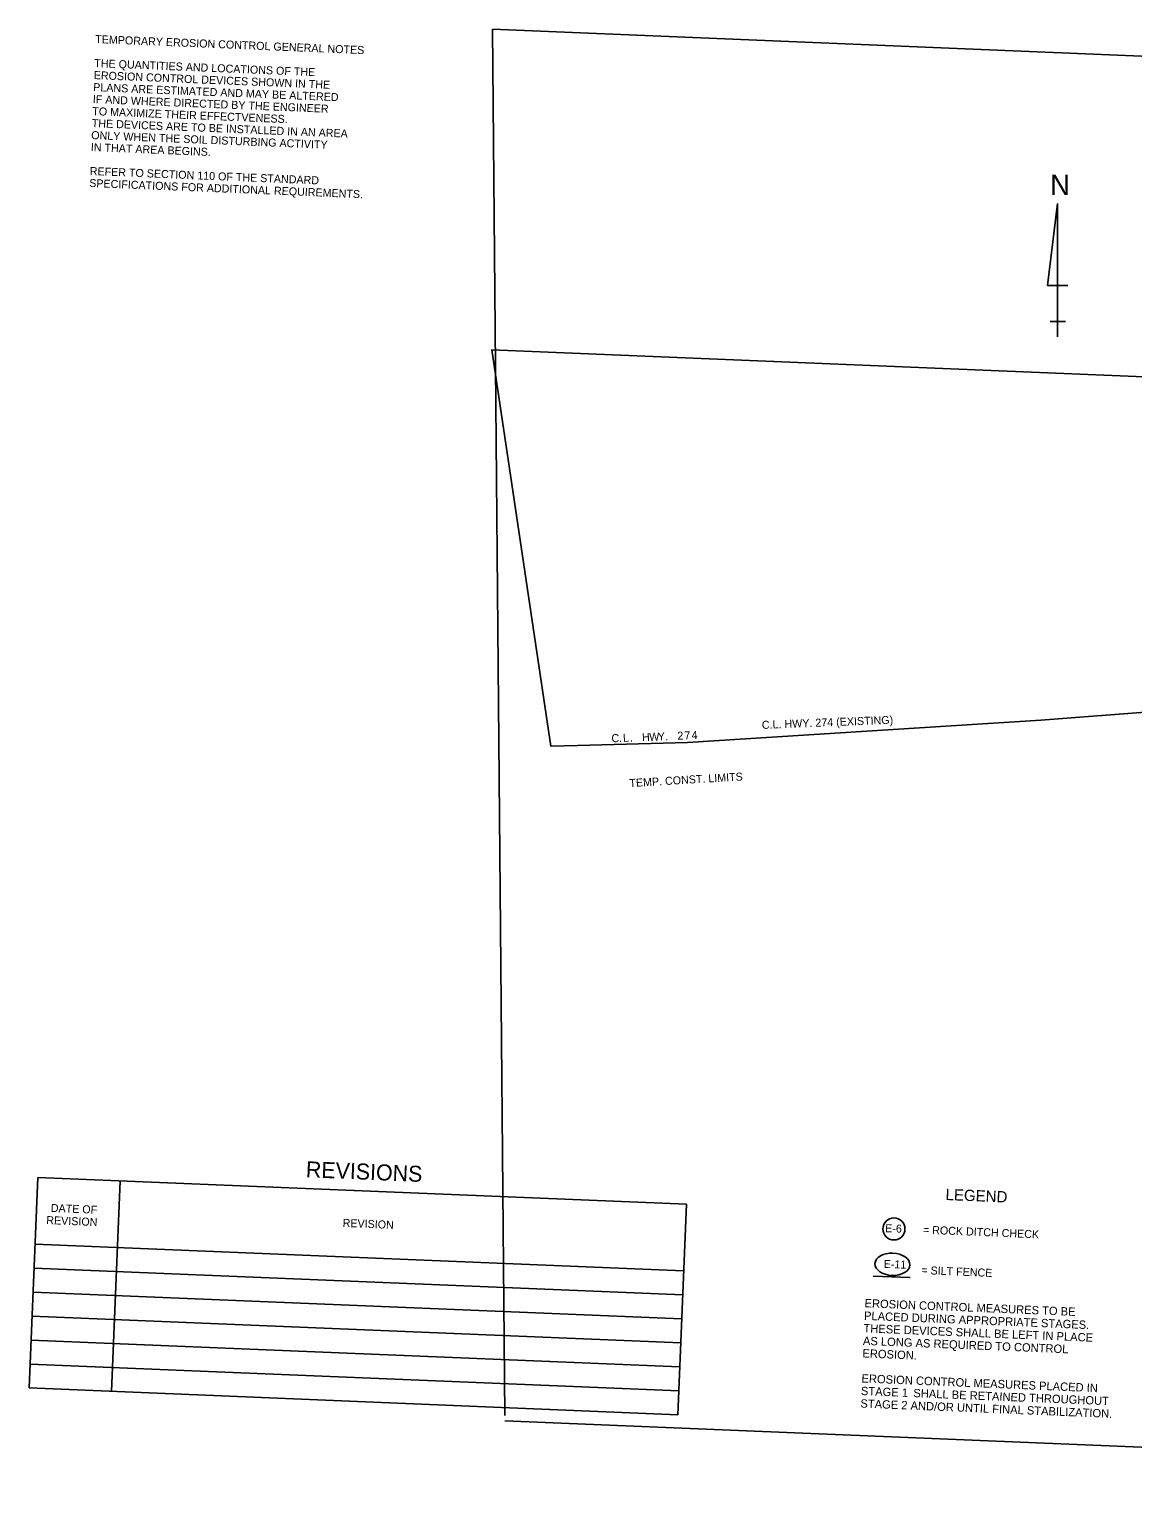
# Model space of a CAD drawing. Extents: x 1141837 to 1143465, y 1657046 to 1658140.
import ezdxf

# ---------------------------------------------------------------- set-up
doc = ezdxf.new("R2010")
doc.units = 0
for name, color, linetype in [('Default', 7, 'Continuous'), ('E_No Plot', 7, 'Continuous'), ('R_Annotation', 7, 'Continuous'), ('R_Erosion', 7, 'Continuous'), ('R_No Plot', 7, 'Continuous'), ('S_BASELINE', 7, 'Continuous')]:
    doc.layers.add(name, color=color, linetype=linetype)

msp = doc.modelspace()

# ---------------------------------------------------------------- linework, layer by layer
at = {"layer": 'Default'}
for p, q in [((1142608.2, 1658009.3), (1142600.5, 1657947.8)), ((1142608.2, 1657909.3), (1142608.2, 1658009.3)), ((1142608.2, 1658009.3), (1142608.2, 1657932.4)), ((1142600.5, 1657947.8), (1142615.9, 1657947.8)), ((1142608.2, 1657909.3), (1142608.2, 1657932.4)), ((1142608.2, 1657920.8), (1142602.5, 1657920.8)), ((1142602.5, 1657920.8), (1142614, 1657920.8)), ((1142608.2, 1657909.3), (1142608.2, 1657920.8))]:
    msp.add_line(p, q, dxfattribs=at)
at = {"layer": 'E_No Plot'}
msp.add_lwpolyline([(1142248.2, 1657602.9), (1142228.1, 1657602.5), (1142228.1, 1657602.5), (1142183.9, 1657899.7), (1143071.8, 1657863), (1143063.8, 1657668.7), (1142853.2, 1657641.8), (1142595.6, 1657621.9), (1142330.5, 1657605.2)], close=True, dxfattribs=at)
at = {"layer": 'R_Erosion'}
msp.add_lwpolyline([(1142469.9, 1657205.2), (1142497.6, 1657204)], dxfattribs=at)
msp.add_circle((1142485.4, 1657240.5), 8.26, dxfattribs=at)
msp.add_ellipse((1142484.3, 1657214), major_axis=(13.1, -0.5), ratio=0.638788, dxfattribs=at)
at = {"layer": 'R_No Plot'}
for p, q in [((1142184.3, 1658140.1), (1142193.6, 1657100.5)), ((1143465.2, 1658087.1), (1142184.3, 1658140.1)), ((1142193.7, 1657096.5), (1143422.1, 1657045.7))]:
    msp.add_line(p, q, dxfattribs=at)
at = {"layer": 'S_BASELINE'}
for p, q in [((1141843.4, 1657279.1), (1141836.9, 1657121.3)), ((1141843.4, 1657279.1), (1142329.8, 1657259)), ((1141905.2, 1657276.6), (1141898.6, 1657118.7)), ((1142329.8, 1657259), (1142323.3, 1657101.1)), ((1141841.3, 1657229.2), (1142327.7, 1657209)), ((1141840.6, 1657211.2), (1142327, 1657191.1)), ((1141839.8, 1657193.2), (1142326.2, 1657173.1)), ((1141839.1, 1657175.2), (1142325.5, 1657155.1)), ((1141838.4, 1657157.2), (1142324.7, 1657137.1)), ((1141837.6, 1657139.2), (1142324, 1657119.1)), ((1141836.9, 1657121.3), (1142323.3, 1657101.1))]:
    msp.add_line(p, q, dxfattribs=at)

# ---------------------------------------------------------------- texts
at = {"layer": 'Default'}
msp.add_text('N', height=15.4, dxfattribs=at).set_placement((1142602.6, 1658015.7))
at = {"layer": 'R_Annotation'}
for s, height, rotation, p in [('TEMPORARY EROSION CONTROL GENERAL NOTES', 6, 357.6311, (1141886.3, 1658129.7)), ('THE QUANTITIES AND LOCATIONS OF THE', 6, 357.6311, (1141885.6, 1658111.7)), ('EROSION CONTROL DEVICES SHOWN IN THE ', 6, 357.6311, (1141885.2, 1658102.7)), ('PLANS ARE ESTIMATED AND MAY BE ALTERED ', 6, 357.6311, (1141884.8, 1658093.7)), ('IF AND WHERE DIRECTED BY THE ENGINEER ', 6, 357.6311, (1141884.5, 1658084.7)), ('THE DEVICES ARE TO BE INSTALLED IN AN AREA ', 6, 357.6311, (1141883.7, 1658066.7)), ('TO MAXIMIZE THEIR EFFECTVENESS. ', 6, 357.6311, (1141884.1, 1658075.7)), ('ONLY WHEN THE SOIL DISTURBING ACTIVITY', 6, 357.6311, (1141883.3, 1658057.7)), ('IN THAT AREA BEGINS.', 6, 357.6311, (1141883, 1658048.7)), ('REFER TO SECTION 110 OF THE STANDARD ', 6, 357.6311, (1141882.2, 1658030.8)), ('SPECIFICATIONS FOR ADDITIONAL REQUIREMENTS.', 6, 357.6311, (1141881.8, 1658021.8)), ('C.L. HWY. 274 (EXISTING) ', 6, 2.2818, (1142386.5, 1657615.4)), ('H', 6, 2.1287, (1142296.6, 1657606.2)), ('W', 6, 2.1827, (1142302, 1657606.4)), ('Y', 6, 2.247, (1142308.4, 1657606.7)), ('2', 6, 2.3941, (1142323.1, 1657607.3)), ('7', 6, 2.4481, (1142328.4, 1657607.5)), ('4', 6, 2.502, (1142333.8, 1657607.7)), ('C', 6, 1.8993, (1142273.7, 1657605.4)), ('.', 6, 1.9561, (1142279.3, 1657605.6)), ('L', 6, 1.9854, (1142282.3, 1657605.7)), ('.', 6, 2.0393, (1142287.6, 1657605.9)), ('.', 6, 2.3047, (1142314.1, 1657606.9)), ('TEMP. CONST. LIMITS', 6, 3.3565, (1142287.2, 1657571.8)), ('= ROCK DITCH CHECK', 6, 357.6311, (1142507.1, 1657237)), ('= SILT FENCE', 6, 357.6311, (1142505.9, 1657206.7)), ('EROSION CONTROL MEASURES TO BE', 6.25, 357.6311, (1142463.3, 1657181.8)), ('PLACED DURING APPROPRIATE STAGES. ', 6.25, 357.6311, (1142462.9, 1657172.4)), ('THESE DEVICES SHALL BE LEFT IN PLACE ', 6.25, 357.6311, (1142462.5, 1657163)), ('AS LONG AS REQUIRED TO CONTROL ', 6.25, 357.6311, (1142462.1, 1657153.6)), ('EROSION.', 6.25, 357.6311, (1142461.7, 1657144.2)), ('EROSION CONTROL MEASURES PLACED IN ', 6.25, 357.6311, (1142461, 1657125.4)), ('STAGE 1 ', 6.25, 357.6311, (1142460.6, 1657116)), ('SHALL BE RETAINED THROUGHOUT ', 6.25, 357.6311, (1142499.9, 1657114.4)), ('STAGE 2 AND/OR UNTIL FINAL STABILIZATION.', 6.25, 357.6311, (1142460.2, 1657106.6))]:
    msp.add_text(s, height=height, rotation=rotation, dxfattribs=at).set_placement(p)
at = {"layer": 'R_Erosion'}
for s, height, rotation, p in [('LEGEND', 8.44, 357.6311, (1142524, 1657262.2)), ('E-6 ', 6, 358.0317, (1142478.8, 1657238.1)), ('E-11', 6, 357.8455, (1142477.7, 1657211.3))]:
    msp.add_text(s, height=height, rotation=rotation, dxfattribs=at).set_placement(p)
at = {"layer": 'S_BASELINE'}
for s, height, p in [('REVISIONS', 12, (1142044.2, 1657279.3)), ('DATE OF', 6, (1141853, 1657253.3)), ('REVISION', 6, (1141849.6, 1657244.2)), ('REVISION', 6, (1142071.9, 1657242.1))]:
    msp.add_text(s, height=height, rotation=357.6311, dxfattribs=at).set_placement(p)

doc.saveas('drawing.dxf')
